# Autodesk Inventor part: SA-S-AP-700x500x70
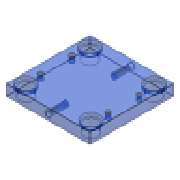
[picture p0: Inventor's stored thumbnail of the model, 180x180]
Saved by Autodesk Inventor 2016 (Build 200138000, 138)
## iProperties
Created: 2015-02
Part Number: SA-S-AP-700x500x70
Material: S 55 C
Description: Cavity Plate
Document SubType Name: Modeling
Designer: Sandeep
Standard Revision: 1
Manufacturer: FUTABA
Language: en-US
Size Designation: 700x500x70
Categories: <MemberInstance><Categories><Category DisplayName="Mold" InternalName="349578f2-f4d4-4954-8c09-8e99297a61c0" Mnemonic="MOLD"><Category DisplayName="Mold Plates"
Density: 7.85 g/cm^3
Appearance: Clear - Blue
IsCustomPart: 1
Author: Sandeep
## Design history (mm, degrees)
sketch "Sketch1"
  geometry: L1 (-250, 350)-(250, 350); L2 (250, 350)-(250, -350); L3 (250, -350)-(-250, -350); L4 (-250, -350)-(-250, 350); 3 further points
  constraints: 8 end point, 2 midpoint, 2 parallel, 1 horizontal, 1 horizontal alignment, 1 perpendicular, 1 vertical alignment
  dimensions: "d123" = 500 distance between parallel lines of L2 L4 (= W_); "d124" = 700 distance between parallel lines of L3 L1 (= L)
extrude "Extrusion1" new body sketch "Sketch1" distance "d20" = 70 (= H_); taper "d30" = 0 deg
sketch "Sketch2"
  geometry: 4 further points
  constraints: 1 horizontal alignment
  dimensions: "d125" = 205 horizontal distance of point (0, 0) point (-205, 243) (= 0.5 x S1_W); "d126" = 243 vertical distance of point (0, 0) point (-205, 243) (= 0.5 x S1_L); "d127" = 207 horizontal distance of point (0, 0) point (-207, 307) (= 0.5 x GB_W); "d128" = 307 vertical distance of point (0, 0) point (-207, 307) (= 0.5 x GB_L); "d129" = 207 horizontal distance of point (0, 0) point (207, 307) (= 0.5 x GB_W)
feature "Sculpt1"
body "Solid1"
sketch "Sketch3"
  geometry: L1 (500, 0)-(0, 0) reference; 3 further points
  constraints: 1 midpoint, 1 vertical alignment
  dimensions: "d169" = 35 distance from line of L1 point (250, 35) (= 0.5 x H_)
hole "Hole1" sketch "Sketch3" diameter "d170" = 31.67; stored, may be unused: countersink angle "d174" = 90 deg, drill point angle "d176" = 118 deg; dims "d171" = 59 (= le), "d172" = 4, "d173" = 2, "d175" = 82 (= ke)
sketch "Sketch4"
  geometry: L1 (0, 0)-(500, 0) reference; 4 further points
  constraints: 2 midpoint, 2 vertical alignment
  dimensions: "d177" = 35 distance from line of L1 point (250, -35) (= 0.5 x H_)
hole "Hole2" sketch "Sketch4" diameter "d178" = 31.67; stored, may be unused: countersink angle "d182" = 90 deg, drill point angle "d184" = 118 deg; dims "d179" = 59 (= le), "d180" = 4, "d181" = 2, "d183" = 82 (= ke)
hole "Hole3" sketch "Sketch2" diameter "d130" = 55 (= GB_d1); stored, may be unused: countersink angle "d134" = 90 deg, drill point angle "d136" = 0 deg; dims "d131" = 6, "d132" = 62 (= GB_d2), "d133" = 10 (= GB_k), "d135" = 70 (= H_)
pattern_linear "Rectangular Pattern1" dims "d159" = 614 (computed from GB_L, Nl)
hole "Hole4" sketch "Sketch2" diameter "d137" = 55 (= GB_d1); stored, may be unused: countersink angle "d141" = 90 deg, drill point angle "d143" = 0 deg; dims "d138" = 6, "d139" = 62 (= GB_d2), "d140" = 10 (= GB_k), "d142" = 70 (= H_)
pattern_linear "Rectangular Pattern2" dims "d162" = 612 (computed from GB_L2, GB_L1, Nl)
hole "Hole5" sketch "Sketch2" diameter "d144" = 13.835; stored, may be unused: countersink angle "d148" = 90 deg, drill point angle "d150" = 118 deg; dims "d145" = 20 (= H_l), "d146" = 62 (= GB_d2), "d147" = 10 (= GB_k), "d149" = 30 (= H_u)
pattern_linear "Rectangular Pattern3" dims "d153" = 243 (computed from S1_L, Ns)
chamfer "Chamfer1" distance "d185" = 0.5; stored, may be unused: second distance "d186" = 2, angle "d187" = 45 deg
feature "Surface1"
body "Srf1"
other parameters: "L" = 700 [user parameter; used in 1 equation term], "W_" = 500 [user parameter; used in 1 equation term], "H_" = 70 [user parameter; used in 5 equation terms], "GB_W" = 414 [user parameter; used in 2 equation terms], "GB_d1" = 55 [user parameter; used in 2 equation terms], "GB_d2" = 62 [user parameter; used in 3 equation terms], "GB_k" = 10 [user parameter; used in 3 equation terms], "S1_L" = 486 [user parameter; used in 2 equation terms], "GB_L1" = 307 [user parameter; used in 1 equation term], "GB_L2" = 305 [user parameter; used in 1 equation term], "GB_L" = 614 [user parameter; used in 2 equation terms], "le" = 59 [user parameter; used in 2 equation terms], "ke" = 82 [user parameter; used in 2 equation terms], "H_l" = 20 [user parameter; used in 1 equation term], "H_u" = 30 [user parameter; used in 1 equation term]
